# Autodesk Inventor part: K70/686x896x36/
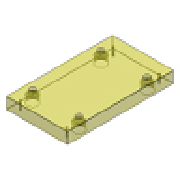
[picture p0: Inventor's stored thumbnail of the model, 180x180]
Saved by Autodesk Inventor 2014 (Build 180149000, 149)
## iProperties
Created: 2009-11
Part Number: K70/686x896x36/
Material: DIN 1.1730
Description: Ejector Plate
Document SubType Name: Modeling
Designer: gaom
Standard Revision: 1
Manufacturer: HASCO
Language: en-US
Size Designation: 686x896x36/
Categories: <MemberInstance><Categories><Category DisplayName="Mold" InternalName="349578f2-f4d4-4954-8c09-8e99297a61c0" Mnemonic="MOLD"><Category DisplayName="Mold Plates"
Density: 7.82 g/cm^3
Appearance: Clear - Yellow
IsCustomPart: 1
Author: gaom
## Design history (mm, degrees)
sketch "Sketch1"
  geometry: L1 (-262, 448)-(262, 448); L2 (262, 448)-(262, -448); L3 (262, -448)-(-262, -448); L4 (-262, -448)-(-262, 448); 5 further points
  constraints: 8 end point, 2 midpoint, 2 parallel, 1 horizontal, 1 horizontal alignment, 1 perpendicular, 1 vertical alignment
  dimensions: "d92" = 405 vertical distance of point (0, 0) point (-244, 405) (= 0.5 x S2_L); "d93" = 244 horizontal distance of point (0, 0) point (-244, 405) (= 0.5 x S2_W); "d94" = 244 horizontal distance of point (0, 0) point (-244, 433) (= 0.5 x SW_W); "d95" = 433 vertical distance of point (0, 0) point (-244, 433) (= 0.5 x SW_L); "d125" = 524 distance between parallel lines of L2 L4 (= W_); "d126" = 896 distance between parallel lines of L3 L1 (= L)
extrude "Extrusion1" new body sketch "Sketch1" distance "d20" = 36 (= H_); taper "d30" = 0 deg
body "Solid1"
hole "Hole1" sketch "Sketch1" diameter "d96" = 3.242; stored, may be unused: countersink angle "d100" = 90 deg, drill point angle "d102" = 118 deg; dims "d97" = 7 (= SW_h1), "d98" = 4, "d99" = 2, "d101" = 12 (= SW_h2)
hole "Hole2" sketch "Sketch1" diameter "d103" = 14 (= S2_d1); stored, may be unused: countersink angle "d107" = 90 deg, drill point angle "d109" = 0 deg; dims "d104" = 6, "d105" = 20 (= S2_d2), "d106" = 15.5 (= S2_k), "d108" = 36 (= H_)
pattern_linear "Rectangular Pattern1" dims "d112" = 866 (computed from SW_L, Nl), "d115" = 488 (computed from SW_W, Nw)
pattern_linear "Rectangular Pattern2" dims "d118" = 810 (computed from S2_L, Nl), "d121" = 488 (computed from S2_W, Nw)
chamfer "Chamfer1" distance "d122" = 0.5; stored, may be unused: second distance "d123" = 2, angle "d124" = 45 deg
other parameters: "L" = 896 [user parameter; used in 1 equation term], "W_" = 524 [user parameter; used in 1 equation term], "H_" = 36 [user parameter; used in 2 equation terms], "S2_W" = 488 [user parameter; used in 2 equation terms], "S2_d1" = 14 [user parameter; used in 1 equation term], "S2_d2" = 20 [user parameter; used in 1 equation term], "S2_k" = 15.5 [user parameter; used in 1 equation term], "SW_L" = 866 [user parameter; used in 2 equation terms], "SW_W" = 488 [user parameter; used in 2 equation terms], "SW_h1" = 7 [user parameter; used in 1 equation term], "SW_h2" = 12 [user parameter; used in 1 equation term], "M_W" = 686 [user parameter], "M_L" = 896 [user parameter], "d134" = 142, "d135" = -279.032, "d136" = 36, "d137" = 0, "d138" = 0, "d139" = -90 deg, "d140" = -78, "d141" = -279.032, "d142" = 36, "d143" = 0, "d144" = 0, "d145" = -90 deg, "d146" = 78, "d147" = 279.032, "d148" = 36, "d149" = 0, "d150" = 0, "d151" = 90 deg, "d152" = -142, "d153" = 279.032, "d154" = 36, "d155" = 0, "d156" = 0, "d157" = 90 deg, "d158" = 154, "d159" = -180.032, "d160" = 36, "d161" = 0, "d162" = 0, "d163" = -90 deg, "d164" = -66, "d165" = -180.032, "d166" = 36, "d167" = 0, "d168" = 0, "d169" = -90 deg, "d170" = 66, "d171" = 180.032, "d172" = 36, "d173" = 0, "d174" = 0, "d175" = 90 deg, "d176" = -154, "d177" = 180.032, "d178" = 36, "d179" = 0, "d180" = 0, "d181" = 90 deg, "d182" = 78, "d183" = -279.032, "d184" = 36, "d185" = 0, "d186" = 0, "d187" = -90 deg, "d188" = -142, "d189" = -279.032, "d190" = 36, "d191" = 0, "d192" = 0, "d193" = -90 deg, "d194" = 142, "d195" = 279.032, "d196" = 36, "d197" = 0, "d198" = 0, "d199" = 90 deg, "d200" = -78, "d201" = 279.032, "d202" = 36, "d203" = 0, "d204" = 0, "d205" = 90 deg, "d206" = 66, "d207" = -180.032, "d208" = 36, "d209" = 0, "d210" = 0, "d211" = -90 deg, "d212" = -154, "d213" = -180.032, "d214" = 36, "d215" = 0, "d216" = 0, "d217" = -90 deg, "d218" = 154, "d219" = 180.032, "d220" = 36, "d221" = 0, "d222" = 0, "d223" = 90 deg, "d224" = -66, "d225" = 180.032, "d226" = 36, "d227" = 0, "d228" = 0, "d229" = 90 deg, "d230" = 154, "d231" = -65.032, "d232" = 36, "d233" = 0, "d234" = 0, "d235" = -90 deg, "d236" = -66, "d237" = -65.032, "d238" = 36, "d239" = 0, "d240" = 0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
